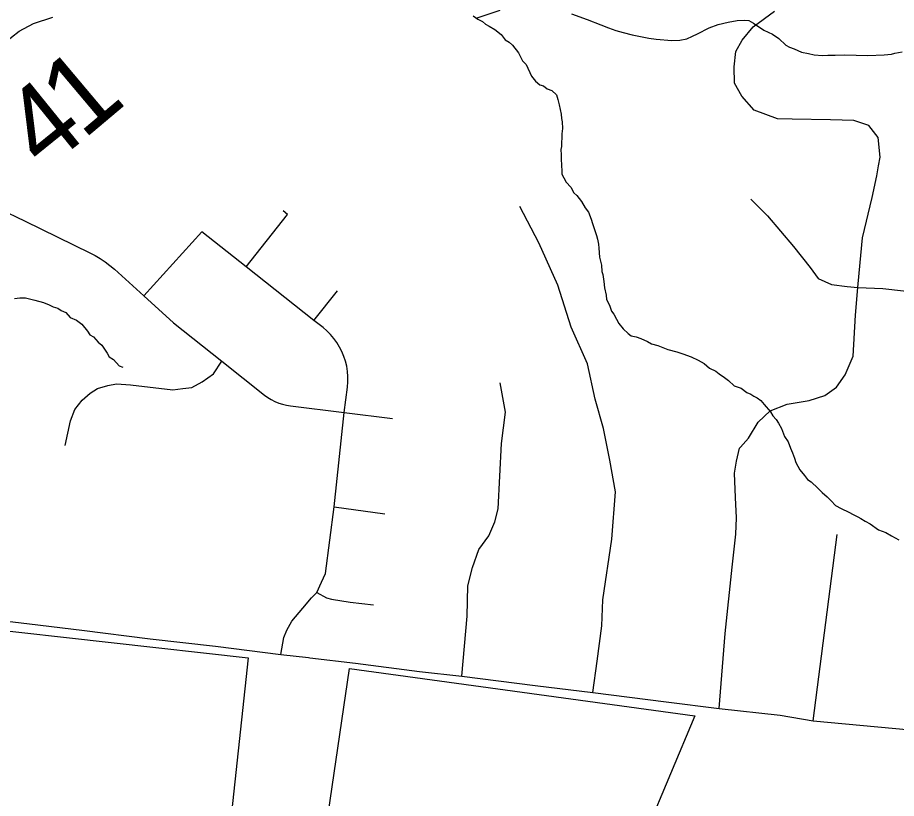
# Model space of a CAD drawing. Extents: x 44.2 to 78.2, y 4.5 to 26.5.
# Drawn here: x 51.106 to 51.74, y 21.923 to 22.487 of the extents above; entities that cross this region are included whole.
import ezdxf

# ---------------------------------------------------------------- set-up
doc = ezdxf.new("R2010")
doc.units = 0
for name, color, linetype in [('GM_X_Corporation', 7, 'Continuous'), ('GM_X_Minor_River', 7, 'Continuous'), ('GM_X_State_Route', 7, 'Continuous'), ('GM_X_Township_Road', 7, 'Continuous'), ('GM_X_Township_Road_Text', 7, 'Continuous')]:
    doc.layers.add(name, color=color, linetype=linetype)

msp = doc.modelspace()

# ---------------------------------------------------------------- linework, layer by layer
at = {"layer": 'GM_X_Corporation'}
msp.add_lwpolyline([(51.07438, 22.04655), (51.27263, 22.02455), (51.25807, 21.8903), (51.32619, 21.88381), (51.34566, 22.01684), (51.59487, 21.98258), (51.54217, 21.85695), (51.54188, 21.7574), (51.56296, 21.77035), (51.58328, 21.63662), (51.53924, 21.60881), (51.4542, 21.56396), (50.97735, 21.44206)], dxfattribs=at)
at = {"layer": 'GM_X_Minor_River'}
for points in [[(51.43718, 22.48614), (51.45435, 22.4918)], [(51.50594, 22.48931), (51.51723, 22.48523), (51.527, 22.48118), (51.53265, 22.47914), (51.53792, 22.4771), (51.5432, 22.47583), (51.54962, 22.47414), (51.5617, 22.47155), (51.56701, 22.47103), (51.57838, 22.46998), (51.58408, 22.47021), (51.58904, 22.47121), (51.59327, 22.473), (51.59673, 22.4748), (51.60519, 22.47913), (51.61171, 22.48162), (51.61897, 22.48332), (51.62545, 22.48429), (51.63078, 22.48453), (51.63381, 22.48445), (51.63718, 22.48247), (51.64465, 22.47734), (51.65104, 22.47452), (51.65551, 22.47137), (51.66071, 22.46668), (51.66333, 22.4651), (51.66672, 22.46387), (51.67198, 22.46146), (51.67689, 22.46057), (51.68105, 22.45971), (51.68711, 22.45917), (51.69092, 22.45945), (51.69623, 22.45931), (51.70307, 22.45951), (51.71977, 22.45907), (51.73156, 22.45952), (51.73689, 22.46014), (51.73919, 22.46084), (51.74453, 22.46184)], [(51.43487, 22.48776), (51.43823, 22.4854), (51.44161, 22.48379), (51.44384, 22.48184), (51.44646, 22.48025), (51.45058, 22.47787), (51.45505, 22.47434), (51.45799, 22.47047), (51.46099, 22.46888), (51.4632, 22.46654), (51.46763, 22.46112), (51.47052, 22.45535), (51.47311, 22.45263), (51.47707, 22.44418), (51.48002, 22.4407), (51.483, 22.43796), (51.48563, 22.43714), (51.48824, 22.43517), (51.49163, 22.43395), (51.49497, 22.43082), (51.49602, 22.42738), (51.49707, 22.42357), (51.49841, 22.4167), (51.49872, 22.41366), (51.49904, 22.41138), (51.49929, 22.40644), (51.49882, 22.40266), (51.49859, 22.39357), (51.49815, 22.3913), (51.49844, 22.3875), (51.49837, 22.38485), (51.49861, 22.37954), (51.49891, 22.37612), (51.49884, 22.37346), (51.50029, 22.37077), (51.50211, 22.36769), (51.50544, 22.36419), (51.50762, 22.35996), (51.50985, 22.35801), (51.51316, 22.35375), (51.5157, 22.34913), (51.51828, 22.34603), (51.52005, 22.34106), (51.52112, 22.33799), (51.52323, 22.33149), (51.52393, 22.3292), (51.52462, 22.32652), (51.5253, 22.32309), (51.5256, 22.32005), (51.5262, 22.31359), (51.52757, 22.30786), (51.52784, 22.30331), (51.52854, 22.30101), (51.52917, 22.29607), (51.52982, 22.2915), (51.53082, 22.28616), (51.53113, 22.28312), (51.5333, 22.27889), (51.53471, 22.27468), (51.53655, 22.27236), (51.53836, 22.2689), (51.54018, 22.26582), (51.54313, 22.26195), (51.54684, 22.25844), (51.54907, 22.25687), (51.55247, 22.25602), (51.55586, 22.25479), (51.56074, 22.25277), (51.56374, 22.25117), (51.56827, 22.24992), (51.57542, 22.24707)], [(51.10385, 22.28368), (51.10766, 22.28434), (51.11183, 22.28423), (51.11863, 22.28253), (51.12466, 22.28086), (51.1288, 22.27924), (51.1318, 22.27764), (51.1352, 22.27679), (51.13743, 22.27521), (51.14081, 22.27361), (51.14414, 22.27011), (51.14865, 22.2681), (51.15238, 22.26534), (51.15643, 22.26031), (51.15826, 22.25761), (51.16088, 22.25602), (51.1642, 22.25214), (51.16681, 22.25018), (51.17084, 22.24438), (51.17229, 22.24169), (51.17528, 22.23971), (51.17934, 22.23506), (51.18198, 22.23423)], [(51.57542, 22.24707), (51.58183, 22.24539), (51.58635, 22.24375), (51.59237, 22.2417), (51.59725, 22.2393), (51.60175, 22.2369), (51.60545, 22.23339), (51.60996, 22.23138), (51.61257, 22.22942), (51.6163, 22.22666), (51.61929, 22.22469), (51.62337, 22.22079), (51.62826, 22.21914), (51.63236, 22.216), (51.63537, 22.21479), (51.63761, 22.21321), (51.63986, 22.21201), (51.64247, 22.21005), (51.64506, 22.20733), (51.64948, 22.2019), (51.65131, 22.1992), (51.65352, 22.19649), (51.65535, 22.19378), (51.65753, 22.18994), (51.65967, 22.18419), (51.66223, 22.18033), (51.66401, 22.17573), (51.66544, 22.17228), (51.66687, 22.16845), (51.66793, 22.16539), (51.67083, 22.16001), (51.67415, 22.15613), (51.67635, 22.15303), (51.67897, 22.15145), (51.68379, 22.14677), (51.68675, 22.14366), (51.69047, 22.14053), (51.69344, 22.1378), (51.69639, 22.13431), (51.70052, 22.1323), (51.70614, 22.1295), (51.70914, 22.1279), (51.71252, 22.1263), (51.71477, 22.1251), (51.71776, 22.12313), (51.7215, 22.12114), (51.72747, 22.11681), (51.73274, 22.11477), (51.73685, 22.11239), (51.7421, 22.1096)]]:
    msp.add_lwpolyline(points, dxfattribs=at)
at = {"layer": 'GM_X_State_Route'}
for points in [[(50.83437, 22.00765), (50.84011, 22.01024), (50.8627, 22.02), (50.9058, 22.0393), (50.91907, 22.04468), (50.93245, 22.04972), (50.94528, 22.05356), (50.95888, 22.05707), (50.96448, 22.05794), (50.97587, 22.05926), (50.98816, 22.05992), (51.00075, 22.06063), (51.01908, 22.05959), (51.03597, 22.05828), (51.11471, 22.04895), (51.15243, 22.04435), (51.20178, 22.03821), (51.24883, 22.03283), (51.2962, 22.02678), (51.31614, 22.02465)], [(51.31614, 22.02465), (51.3171, 22.02453), (51.3499, 22.02056), (51.39618, 22.01457), (51.42665, 22.01127), (51.47966, 22.00438), (51.52127, 21.99949), (51.57413, 21.99271), (51.61245, 21.98797), (51.65647, 21.98294), (51.68041, 21.97908), (51.75036, 21.97243), (51.83433, 21.96194), (51.87331, 21.95519), (51.9078, 21.95069), (51.95616, 21.94469), (51.99477, 21.94057), (52.05381, 21.93514), (52.09012, 21.92978)]]:
    msp.add_lwpolyline(points, dxfattribs=at)
at = {"layer": 'GM_X_Township_Road'}
for p, q in [((51.19726, 22.2856), (51.23912, 22.33194)), ((51.32001, 22.26797), (51.33689, 22.28931)), ((51.33466, 22.13333), (51.37105, 22.12837)), ((51.68041, 21.97908), (51.69763, 22.11348))]:
    msp.add_line(p, q, dxfattribs=at)
for points in [[(51.7276, 22.37948), (51.72881, 22.38571), (51.72731, 22.39996), (51.72056, 22.40858), (51.70969, 22.41233), (51.69282, 22.4127), (51.66508, 22.41308), (51.65458, 22.41346), (51.63772, 22.41964), (51.62893, 22.42978), (51.62366, 22.43913), (51.62328, 22.45094), (51.6246, 22.462), (51.62909, 22.47024), (51.63697, 22.47981), (51.65233, 22.49105)], [(50.9773, 22.43331), (50.98435, 22.43546), (50.99287, 22.4375), (51.00174, 22.43852), (51.01179, 22.44074), (51.0181, 22.44227), (51.02611, 22.44278), (51.03906, 22.44449), (51.04928, 22.44602), (51.06019, 22.44705), (51.06667, 22.4479), (51.07416, 22.45114), (51.08013, 22.45454), (51.0878, 22.46051), (51.09547, 22.46732), (51.10177, 22.47227), (51.10723, 22.4767), (51.11762, 22.48215), (51.13143, 22.48675)], [(51.62793, 22.17658), (51.63359, 22.18291), (51.64062, 22.19448), (51.64941, 22.20277), (51.66152, 22.20742), (51.67745, 22.21007), (51.6887, 22.21365), (51.6972, 22.21969), (51.70332, 22.22865), (51.70924, 22.2421), (51.71081, 22.27176), (51.71269, 22.29162), (51.71344, 22.30212), (51.71606, 22.32761), (51.72296, 22.35657), (51.72618, 22.37222), (51.7276, 22.37948)], [(51.63528, 22.35535), (51.64746, 22.34335), (51.66602, 22.32124), (51.6782, 22.30624), (51.68387, 22.29817), (51.69357, 22.29387), (51.70481, 22.29238), (51.71269, 22.29162), (51.7305, 22.29106), (51.74549, 22.28919), (51.75861, 22.28769), (51.78597, 22.27569)], [(51.0906, 22.34519), (51.09234, 22.34877), (51.1115, 22.33948), (51.15821, 22.31682), (51.16201, 22.31484), (51.16569, 22.31265), (51.16925, 22.31025), (51.17266, 22.30766), (51.17592, 22.30488), (51.19726, 22.2856), (51.21864, 22.2663), (51.25355, 22.23843), (51.2843, 22.21411), (51.28669, 22.21237), (51.2892, 22.21082), (51.29184, 22.20947), (51.29457, 22.20833), (51.29738, 22.2074), (51.30025, 22.2067), (51.30317, 22.20623), (51.34189, 22.20147), (51.37667, 22.19719)], [(51.52127, 21.99949), (51.52451, 22.0221), (51.52789, 22.04759), (51.52863, 22.06633), (51.53498, 22.11002), (51.53763, 22.1443), (51.5335, 22.16717), (51.52901, 22.19004), (51.52301, 22.21103), (51.51738, 22.23652), (51.50577, 22.26313), (51.4961, 22.29349), (51.48225, 22.3239), (51.46866, 22.3501)], [(51.27099, 22.30674), (51.30083, 22.34447), (51.29771, 22.34694)], [(51.2962, 22.02678), (51.29827, 22.03903), (51.3005, 22.04448), (51.30397, 22.05091), (51.31189, 22.06032), (51.31832, 22.06774), (51.32203, 22.0717), (51.3255, 22.07913), (51.32822, 22.08532), (51.33466, 22.13333), (51.34189, 22.20147), (51.34416, 22.21989), (51.34446, 22.22363), (51.34447, 22.2255), (51.34448, 22.22738), (51.34419, 22.23111), (51.34362, 22.23482), (51.34275, 22.23844), (51.34161, 22.24198), (51.34019, 22.24542), (51.33851, 22.24873), (51.33657, 22.25191), (51.33439, 22.25492), (51.33198, 22.25775), (51.32936, 22.26039), (51.32653, 22.26281), (51.32001, 22.26797), (51.27099, 22.30674), (51.23912, 22.33194)], [(51.1405, 22.17764), (51.14421, 22.19546), (51.14743, 22.20363), (51.15262, 22.21031), (51.15856, 22.21551), (51.16376, 22.21873), (51.17119, 22.22095), (51.17738, 22.22219), (51.18752, 22.22145), (51.21821, 22.21774), (51.22539, 22.21873), (51.23183, 22.21947), (51.23925, 22.22368), (51.24742, 22.22937), (51.25355, 22.23843)], [(51.42665, 22.01127), (51.4307, 22.05446), (51.43105, 22.07629), (51.43454, 22.08958), (51.43904, 22.1027), (51.44616, 22.11245), (51.45066, 22.12256), (51.45291, 22.13194), (51.4554, 22.17914), (51.45816, 22.20166), (51.45441, 22.22302)], [(51.61245, 21.98797), (51.61672, 22.04197), (51.62197, 22.08995), (51.6246, 22.11357), (51.62497, 22.12556), (51.62422, 22.14018), (51.62347, 22.1578), (51.62497, 22.16642), (51.62722, 22.17579), (51.62793, 22.17658)], [(51.32203, 22.0717), (51.32897, 22.06773), (51.33269, 22.06674), (51.34605, 22.06451), (51.36288, 22.06278)]]:
    msp.add_lwpolyline(points, dxfattribs=at)

# ---------------------------------------------------------------- texts
at = {"layer": 'GM_X_Township_Road_Text'}
for s, rotation, p in [('1', 40.09835, (51.15333, 22.39782)), ('4', 38.99289, (51.12521, 22.37504))]:
    msp.add_text(s, height=0.05682, rotation=rotation, dxfattribs=at).set_placement(p)

doc.saveas('drawing.dxf')
